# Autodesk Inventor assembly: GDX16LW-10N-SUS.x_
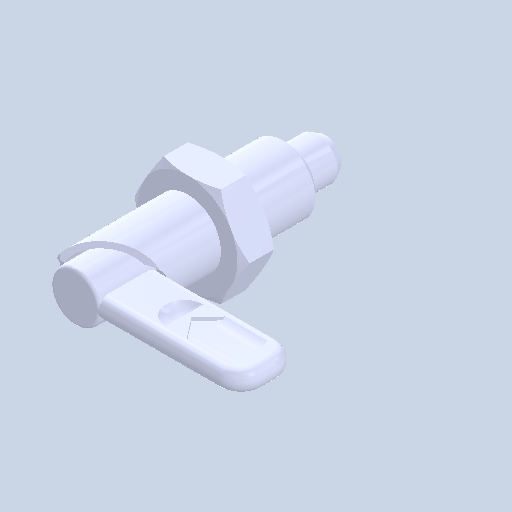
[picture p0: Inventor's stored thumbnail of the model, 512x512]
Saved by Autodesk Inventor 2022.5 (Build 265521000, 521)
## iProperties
Created: 2024-06
Part Number: GDX16LW-10N-SUS.x_
Document SubType Name: Assembly
Designer: ImaoCorp
Author: ImaoCorp
Sending System: SOLIDWORKS 2022-2022290
MC: AMD64
MC_MODEL: Intel64 Family 6 Model 60 Stepping 3, GenuineIntel
OS: Windows_NT
FRU: Parasolid Version 33.1, build 260,  4-25-2022
FORMAT: text
GUISE: transmit
KEY: FILEGDX16LW-10N-SUS.x_t
DATE: Wed Jun 12 09:32:30 2024
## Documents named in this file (4)
- Y:\5.更新分\2024年対応\xxxx_GDX\データ_imao品番\gdx16lw-10n-sus\GDX16LW-10N-SUS.x_.iam
- Y:\5.更新分\2024年対応\xxxx_GDX\データ_imao品番\gdx16lw-10n-sus\GDX16LW-10N-SUS_01.ipt
- Y:\5.更新分\2024年対応\xxxx_GDX\データ_imao品番\gdx16lw-10n-sus\GDX16LW-10N-SUS_02.ipt
- Y:\5.更新分\2024年対応\xxxx_GDX\データ_imao品番\gdx16lw-10n-sus\GDX16LW-10N-SUS_03.ipt
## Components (3 placed, 3 different names)
1. GDX16LW-10N-SUS_01
2. GDX16LW-10N-SUS_02
3. GDX16LW-10N-SUS_03
